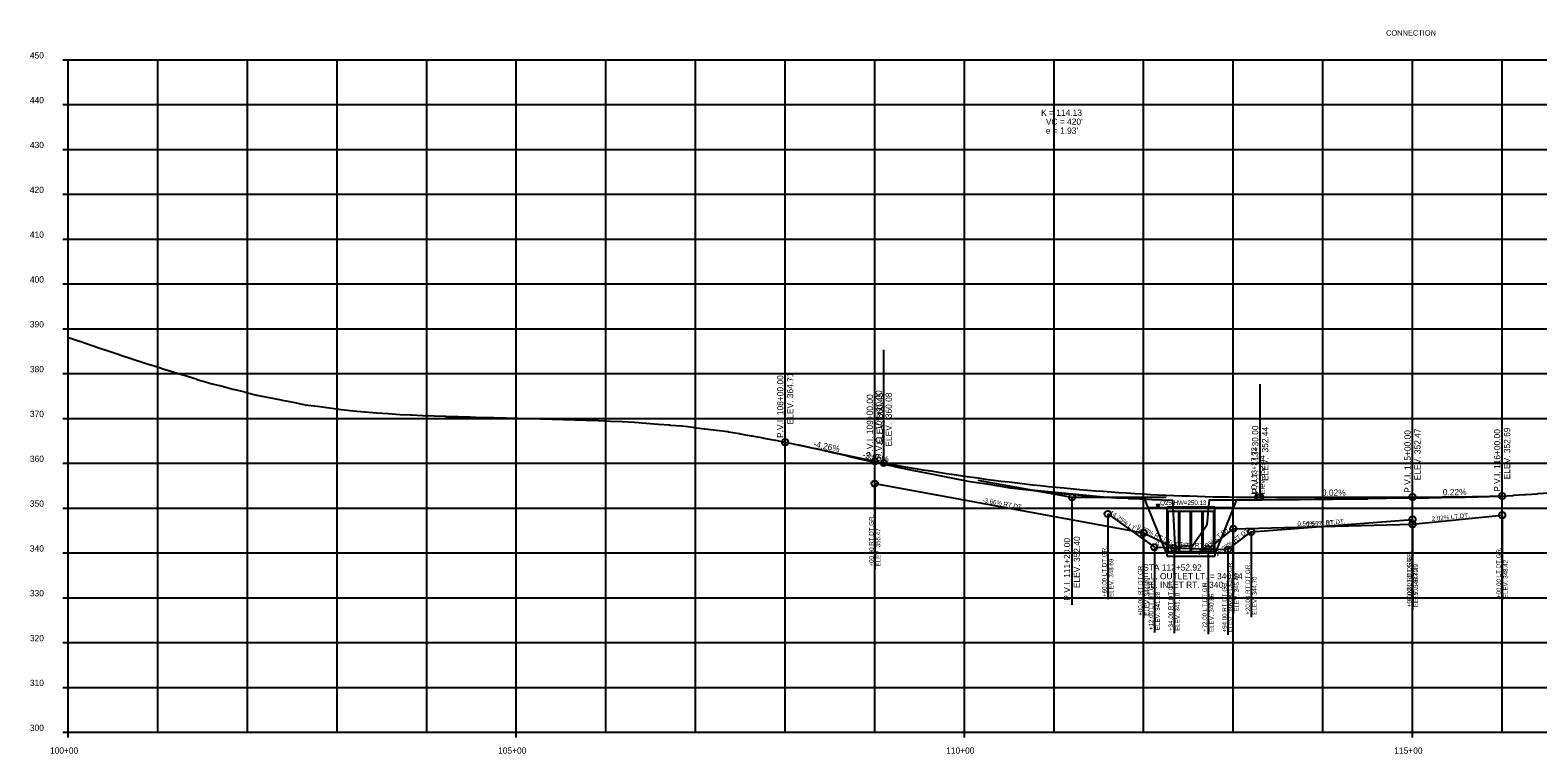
# Model space of a CAD drawing. Extents: x 1627557 to 1636561, y 783843 to 794002.
# Drawn here: x 1633050 to 1634732, y 793194 to 794002 of the extents above; entities that cross this region are included whole.
import ezdxf

# ---------------------------------------------------------------- set-up
doc = ezdxf.new("R2010")
doc.units = 0
for name, color, linetype in [('R_Axis', 7, 'Continuous'), ('R_Axis Annot', 7, 'Continuous'), ('R_Culvert', 7, 'Continuous'), ('R_Exist Surface', 7, 'Continuous'), ('R_Fin Surface', 7, 'Continuous'), ('R_Grid', 7, 'Continuous'), ('R_No Plot', 7, 'Continuous'), ('R_Vert Alg', 7, 'Continuous'), ('R_Vert Alg Annot', 7, 'Continuous'), ('R_Vert Alg LP', 7, 'Continuous'), ('R_Vert Alg LP Annot', 7, 'Continuous'), ('R_Vert Ditch Alg', 7, 'Continuous'), ('R_Vert Ditch Alg Annot', 7, 'Continuous'), ('RC Box Annot', 7, 'Continuous')]:
    doc.layers.add(name, color=color, linetype=linetype)

msp = doc.modelspace()

# ---------------------------------------------------------------- linework, layer by layer
at = {"layer": 'R_Axis'}
for p, q in [((1633086.6, 793968.6), (1633092.6, 793968.6)), ((1633086.6, 793968.6), (1633092.6, 793968.6)), ((1633092.6, 793218.6), (1633092.6, 793968.6)), ((1633086.6, 793918.6), (1633092.6, 793918.6)), ((1633086.6, 793868.6), (1633092.6, 793868.6)), ((1633086.6, 793818.6), (1633092.6, 793818.6)), ((1633086.6, 793768.6), (1633092.6, 793768.6)), ((1633086.6, 793718.6), (1633092.6, 793718.6)), ((1633086.6, 793668.6), (1633092.6, 793668.6)), ((1633086.6, 793618.6), (1633092.6, 793618.6)), ((1633086.6, 793568.6), (1633092.6, 793568.6)), ((1633086.6, 793518.6), (1633092.6, 793518.6)), ((1633086.6, 793468.6), (1633092.6, 793468.6)), ((1633086.6, 793418.6), (1633092.6, 793418.6)), ((1633086.6, 793368.6), (1633092.6, 793368.6)), ((1633086.6, 793318.6), (1633092.6, 793318.6)), ((1633086.6, 793268.6), (1633092.6, 793268.6)), ((1633086.6, 793218.6), (1633092.6, 793218.6)), ((1633092.6, 793218.6), (1636092.6, 793218.6)), ((1633092.6, 793212.6), (1633092.6, 793218.6)), ((1633592.6, 793212.6), (1633592.6, 793218.6)), ((1634092.6, 793212.6), (1634092.6, 793218.6)), ((1634592.6, 793212.6), (1634592.6, 793218.6))]:
    msp.add_line(p, q, dxfattribs=at)
at = {"layer": 'R_Culvert'}
for p, q in [((1634297.8, 793469.2), (1634393.2, 793469.2)), ((1634319, 793420), (1634319, 793470)), ((1634319, 793470), (1634372, 793470)), ((1634319, 793465), (1634372, 793465)), ((1634320, 793420), (1634320, 793465)), ((1634332, 793420), (1634332, 793465)), ((1634333, 793420), (1634333, 793465)), ((1634345, 793420), (1634345, 793465)), ((1634346, 793420), (1634346, 793465)), ((1634358, 793420), (1634358, 793465)), ((1634359, 793420), (1634359, 793465)), ((1634371, 793420), (1634371, 793465)), ((1634372, 793420), (1634372, 793470)), ((1634319, 793420), (1634372, 793420)), ((1634319, 793415), (1634319, 793420)), ((1634319, 793415), (1634372, 793415)), ((1634372, 793420), (1634372, 793415))]:
    msp.add_line(p, q, dxfattribs=at)
msp.add_lwpolyline([(1634308.5, 793469.2), (1634310.2, 793472.2), (1634306.8, 793472.2)], close=True, dxfattribs=at)
at = {"layer": 'R_Exist Surface'}
msp.add_lwpolyline([(1633092.6, 793659), (1633092.8, 793658.9), (1633105.4, 793654.6), (1633105.6, 793654.6), (1633118.3, 793650.3), (1633118.4, 793650.3), (1633131.1, 793646), (1633131.1, 793646), (1633132.8, 793645.4), (1633143.9, 793641.6), (1633144, 793641.6), (1633157.1, 793637.3), (1633157.2, 793637.3), (1633170.3, 793633), (1633170.5, 793633), (1633178.5, 793630.4), (1633183.5, 793628.8), (1633183.8, 793628.7), (1633196.6, 793624.5), (1633197, 793624.4), (1633209.9, 793620.4), (1633210.3, 793620.3), (1633223.2, 793616.4), (1633223.5, 793616.3), (1633236.4, 793612.3), (1633236.7, 793612.2), (1633249.7, 793608.2), (1633249.9, 793608.1), (1633263, 793604.8), (1633263.2, 793604.8), (1633276.3, 793601.4), (1633276.5, 793601.4), (1633289.6, 793598.1), (1633289.7, 793598), (1633302.8, 793594.7), (1633303, 793594.7), (1633316.5, 793592), (1633316.5, 793592), (1633330.1, 793589.3), (1633330.1, 793589.3), (1633331.2, 793589.1), (1633343.6, 793586.6), (1633343.6, 793586.6), (1633357.1, 793583.9), (1633357.2, 793583.9), (1633370.3, 793582.1), (1633370.5, 793582.1), (1633370.7, 793582.1), (1633383.8, 793580.4), (1633384, 793580.4), (1633397.1, 793578.6), (1633397.4, 793578.6), (1633410.4, 793576.9), (1633410.7, 793576.9), (1633423.4, 793575.9), (1633423.9, 793575.9), (1633436.5, 793575), (1633437, 793574.9), (1633449.5, 793574), (1633450.1, 793574), (1633462.6, 793573), (1633474.7, 793572.5), (1633475.3, 793572.5), (1633476, 793572.5), (1633488, 793572), (1633488.7, 793572), (1633500.8, 793571.5), (1633501.5, 793571.4), (1633513.5, 793571), (1633514.3, 793570.9), (1633527, 793570.6), (1633527.8, 793570.6), (1633540.6, 793570.2), (1633541.3, 793570.2), (1633554.1, 793569.8), (1633554.8, 793569.8), (1633567.6, 793569.5), (1633580, 793569.2), (1633580.6, 793569.2), (1633581.2, 793569.1), (1633593.6, 793568.8), (1633594.2, 793568.8), (1633606.7, 793568.5), (1633607.2, 793568.5), (1633619.7, 793568.2), (1633620.1, 793568.2), (1633632.5, 793567.8), (1633632.9, 793567.8), (1633645.4, 793567.4), (1633645.6, 793567.4), (1633658.2, 793567), (1633658.3, 793567), (1633670.6, 793566.7), (1633671, 793566.7), (1633671, 793566.7), (1633684.3, 793566.1), (1633684.4, 793566.1), (1633697.6, 793565.5), (1633697.8, 793565.5), (1633710.9, 793565), (1633711.2, 793565), (1633724.2, 793564.4), (1633724.6, 793564.4), (1633737.4, 793563.4), (1633737.9, 793563.3), (1633750.5, 793562.3), (1633751.1, 793562.3), (1633763.7, 793561.3), (1633764.4, 793561.2), (1633776.8, 793560.3), (1633777.6, 793560.2), (1633789.8, 793558.7), (1633790.6, 793558.6), (1633802.7, 793557.1), (1633803.5, 793557), (1633815.6, 793555.5), (1633816.4, 793555.4), (1633828.5, 793553.9), (1633829.3, 793553.8), (1633841.7, 793551.6), (1633842.4, 793551.4), (1633854.8, 793549.2), (1633855.6, 793549.1), (1633868, 793546.8), (1633868.7, 793546.7), (1633881.2, 793544.5), (1633881.8, 793544.4), (1633894.1, 793541.8), (1633894.6, 793541.7), (1633906.9, 793539.1), (1633907.5, 793539), (1633919.8, 793536.4), (1633920.3, 793536.3), (1633932.7, 793533.8), (1633933.2, 793533.7), (1633946.9, 793530.4), (1633947.3, 793530.3), (1633961, 793527.1), (1633961.5, 793527), (1633961.6, 793527), (1633975.3, 793523.7), (1633975.7, 793523.6), (1633989.5, 793520.4), (1633989.8, 793520.3), (1634013.7, 793515.2), (1634014.1, 793515.1), (1634038.1, 793510), (1634038.4, 793510), (1634051.5, 793507.4), (1634051.6, 793507.4), (1634051.7, 793507.4), (1634064.8, 793504.8), (1634064.8, 793504.8), (1634077.9, 793502.2), (1634078, 793502.2), (1634085.3, 793500.8), (1634091.1, 793499.6), (1634091.1, 793499.6), (1634096.3, 793498.8), (1634104.3, 793497.5), (1634104.4, 793497.5), (1634117.5, 793495.5), (1634130.6, 793493.4), (1634130.8, 793493.4), (1634143.8, 793491.3), (1634144, 793491.3), (1634157.2, 793489.8), (1634157.4, 793489.8), (1634170.5, 793488.2), (1634170.8, 793488.2), (1634183.9, 793486.7), (1634184.2, 793486.6), (1634184.5, 793486.6), (1634197.6, 793485.1), (1634198, 793485), (1634210.5, 793484), (1634223.2, 793482.9), (1634223.5, 793482.9), (1634236.2, 793481.8), (1634236.4, 793481.8), (1634249.2, 793480.7), (1634249.4, 793480.7), (1634262.5, 793480.1), (1634262.6, 793480.1), (1634275.8, 793479.5), (1634275.8, 793479.4), (1634275.9, 793479.4), (1634281.9, 793479.2), (1634289, 793478.8), (1634289.1, 793478.8), (1634302.2, 793478.2), (1634302.3, 793478.2), (1634324.5, 793477.6), (1634324.8, 793477.6), (1634327.5, 793426), (1634327.6, 793424.5), (1634327.6, 793424.5), (1634327.9, 793424.5), (1634338.5, 793427), (1634346.7, 793426.3), (1634362.8, 793449), (1634363.2, 793449.2), (1634363.3, 793450), (1634363.4, 793450.2), (1634366, 793477.7), (1634379.2, 793477.7), (1634379.4, 793477.7), (1634392.6, 793477.7), (1634392.8, 793477.7), (1634393, 793477.7), (1634406.2, 793477.8), (1634406.3, 793477.8), (1634419.6, 793477.8), (1634419.7, 793477.8), (1634441.3, 793478), (1634441.4, 793478), (1634463.1, 793478.3), (1634463.1, 793478.3), (1634463.1, 793478.3), (1634466.4, 793478.3), (1634483, 793478.5), (1634483.1, 793478.5), (1634502.8, 793478.7), (1634503, 793478.7), (1634503.2, 793478.7), (1634522.8, 793478.9), (1634523.1, 793478.9), (1634542.5, 793479), (1634542.9, 793479), (1634543.3, 793479.1), (1634563.2, 793479.5), (1634563.6, 793479.5), (1634583.4, 793479.9), (1634583.8, 793479.9), (1634596.7, 793480.1), (1634597.4, 793480.1), (1634610.2, 793480.2), (1634611, 793480.2), (1634623.8, 793480.4), (1634624.7, 793480.4), (1634637.4, 793480.6), (1634638.4, 793480.6), (1634651.2, 793480.9), (1634663.9, 793481.3), (1634665.2, 793481.3), (1634677.9, 793481.6), (1634679.3, 793481.7), (1634692, 793482), (1634704.5, 793482.8), (1634705.4, 793482.9), (1634718.1, 793483.7), (1634718.9, 793483.8), (1634731.6, 793484.6), (1634732.4, 793484.7), (1634745.1, 793485.5)], dxfattribs=at)
at = {"layer": 'R_Fin Surface'}
for p, q in [((1634373.5, 793420), (1634396.6, 793477.7)), ((1634372, 793420), (1634373.5, 793420))]:
    msp.add_line(p, q, dxfattribs=at)
msp.add_lwpolyline([(1634319, 793420), (1634317.5, 793420), (1634294, 793478.6)], dxfattribs=at)
at = {"layer": 'R_Grid'}
for p, q in [((1633092.6, 793968.6), (1636092.6, 793968.6)), ((1633092.6, 793968.6), (1636092.6, 793968.6)), ((1633192.6, 793218.6), (1633192.6, 793968.6)), ((1633292.6, 793218.6), (1633292.6, 793968.6)), ((1633392.6, 793218.6), (1633392.6, 793968.6)), ((1633492.6, 793218.6), (1633492.6, 793968.6)), ((1633592.6, 793218.6), (1633592.6, 793968.6)), ((1633692.6, 793218.6), (1633692.6, 793968.6)), ((1633792.6, 793218.6), (1633792.6, 793968.6)), ((1633892.6, 793218.6), (1633892.6, 793968.6)), ((1633992.6, 793218.6), (1633992.6, 793968.6)), ((1634092.6, 793218.6), (1634092.6, 793968.6)), ((1634192.6, 793218.6), (1634192.6, 793968.6)), ((1634292.6, 793218.6), (1634292.6, 793968.6)), ((1634392.6, 793218.6), (1634392.6, 793968.6)), ((1634492.6, 793218.6), (1634492.6, 793968.6)), ((1634592.6, 793218.6), (1634592.6, 793968.6)), ((1634692.6, 793218.6), (1634692.6, 793968.6)), ((1633092.6, 793918.6), (1636092.6, 793918.6)), ((1633092.6, 793868.6), (1636092.6, 793868.6)), ((1633092.6, 793818.6), (1636092.6, 793818.6)), ((1633092.6, 793768.6), (1636092.6, 793768.6)), ((1633092.6, 793718.6), (1636092.6, 793718.6)), ((1633092.6, 793668.6), (1636092.6, 793668.6)), ((1633092.6, 793618.6), (1636092.6, 793618.6)), ((1633092.6, 793568.6), (1636092.6, 793568.6)), ((1633092.6, 793518.6), (1636092.6, 793518.6)), ((1633092.6, 793468.6), (1636092.6, 793468.6)), ((1633092.6, 793418.6), (1636092.6, 793418.6)), ((1633092.6, 793368.6), (1636092.6, 793368.6)), ((1633092.6, 793318.6), (1636092.6, 793318.6)), ((1633092.6, 793268.6), (1636092.6, 793268.6))]:
    msp.add_line(p, q, dxfattribs=at)
at = {"layer": 'R_Vert Alg'}
for p, q in [((1633892.6, 793542.1), (1633892.6, 793662.1)), ((1634002.6, 793519), (1634002.6, 793645)), ((1633992.6, 793520.8), (1633992.6, 793640.8)), ((1634422.6, 793480.8), (1634422.6, 793606.8)), ((1634592.6, 793480.9), (1634592.6, 793600.9)), ((1634692.6, 793482), (1634692.6, 793602)), ((1633892.6, 793542.1), (1633992.6, 793520.8)), ((1633992.6, 793520.8), (1634002.6, 793519)), ((1634107.6, 793499.8), (1634212.6, 793480.6)), ((1634212.6, 793480.6), (1634317.6, 793480.7)), ((1634212.6, 793480.6), (1634212.6, 793360.6)), ((1634422.6, 793480.8), (1634592.6, 793480.9)), ((1634592.6, 793480.9), (1634692.6, 793482))]:
    msp.add_line(p, q, dxfattribs=at)
msp.add_lwpolyline([(1634002.6, 793519), (1634011.3, 793517.4), (1634020.1, 793515.9), (1634028.8, 793514.3), (1634037.6, 793512.9), (1634046.3, 793511.4), (1634055.1, 793510), (1634063.8, 793508.6), (1634072.6, 793507.3), (1634081.3, 793505.9), (1634090.1, 793504.7), (1634098.8, 793503.4), (1634107.6, 793502.2), (1634116.3, 793501), (1634125.1, 793499.9), (1634133.8, 793498.8), (1634142.6, 793497.7), (1634151.3, 793496.6), (1634160.1, 793495.6), (1634168.8, 793494.6), (1634177.6, 793493.7), (1634186.3, 793492.8), (1634195.1, 793491.9), (1634203.8, 793491), (1634221.3, 793489.4), (1634230.1, 793488.7), (1634238.8, 793488), (1634247.6, 793487.3), (1634256.3, 793486.7), (1634265.1, 793486.1), (1634273.8, 793485.5), (1634282.6, 793484.9), (1634291.3, 793484.4), (1634300.1, 793483.9), (1634308.8, 793483.5), (1634317.6, 793483.1), (1634326.3, 793482.7), (1634335.1, 793482.4), (1634343.8, 793482.1), (1634352.6, 793481.8), (1634361.3, 793481.5), (1634370.1, 793481.3), (1634378.8, 793481.2), (1634387.6, 793481), (1634396.3, 793480.9), (1634405.1, 793480.8), (1634413.8, 793480.8), (1634422.6, 793480.8)], dxfattribs=at)
for centre in [(1633892.6, 793542.1), (1633992.6, 793520.8), (1634002.6, 793519), (1634212.6, 793480.6), (1634422.6, 793480.8), (1634592.6, 793480.9), (1634692.6, 793482)]:
    msp.add_circle(centre, 3.5, dxfattribs=at)
at = {"layer": 'R_Vert Alg Annot'}
msp.add_line((1634151.6, 793490.4), (1634251.6, 793480.6), dxfattribs=at)
at = {"layer": 'R_Vert Alg LP'}
msp.add_circle((1634420.3, 793480.8), 3.5, dxfattribs=at)
at = {"layer": 'R_Vert Ditch Alg'}
for p, q in [((1633992.6, 793495.9), (1633992.6, 793485.9)), ((1633992.6, 793495.9), (1634292.6, 793441)), ((1633992.6, 793485.9), (1633992.6, 793400.9)), ((1634252.6, 793462), (1634252.6, 793452)), ((1634252.6, 793462), (1634304.6, 793425)), ((1634592.6, 793450.6), (1634692.6, 793460.7)), ((1634692.6, 793460.7), (1634692.6, 793450.7)), ((1634252.6, 793452), (1634252.6, 793367)), ((1634364.6, 793422.9), (1634392.6, 793445.6)), ((1634392.6, 793445.6), (1634592.6, 793450.6)), ((1634392.6, 793445.6), (1634392.6, 793435.6)), ((1634412.6, 793442.1), (1634592.6, 793456)), ((1634592.6, 793456), (1634592.6, 793446)), ((1634592.6, 793450.6), (1634592.6, 793440.6)), ((1634592.6, 793446), (1634592.6, 793361)), ((1634692.6, 793450.7), (1634692.6, 793365.7)), ((1634292.6, 793441), (1634292.6, 793431)), ((1634292.6, 793441), (1634326.6, 793424.1)), ((1634292.6, 793431), (1634292.6, 793346)), ((1634386.6, 793422.3), (1634412.6, 793442.1)), ((1634392.6, 793435.6), (1634392.6, 793350.6)), ((1634412.6, 793442.1), (1634412.6, 793432.1)), ((1634412.6, 793432.1), (1634412.6, 793347.1)), ((1634592.6, 793440.6), (1634592.6, 793355.6)), ((1634304.6, 793425), (1634304.6, 793415)), ((1634304.6, 793425), (1634364.6, 793422.9)), ((1634304.6, 793415), (1634304.6, 793330)), ((1634326.6, 793424.1), (1634326.6, 793414.1)), ((1634326.6, 793424.1), (1634386.6, 793422.3)), ((1634326.6, 793414.1), (1634326.6, 793329.1)), ((1634364.6, 793422.9), (1634364.6, 793412.9)), ((1634364.6, 793412.9), (1634364.6, 793327.9)), ((1634386.6, 793422.3), (1634386.6, 793412.3)), ((1634386.6, 793412.3), (1634386.6, 793327.3))]:
    msp.add_line(p, q, dxfattribs=at)
for centre in [(1633992.6, 793495.9), (1634252.6, 793462), (1634592.6, 793456), (1634692.6, 793460.7), (1634292.6, 793441), (1634392.6, 793445.6), (1634412.6, 793442.1), (1634592.6, 793450.6), (1634304.6, 793425), (1634326.6, 793424.1), (1634364.6, 793422.9), (1634386.6, 793422.3)]:
    msp.add_circle(centre, 3.5, dxfattribs=at)

# ---------------------------------------------------------------- texts
at = {"layer": 'R_Axis Annot'}
for s, p in [('450', (1633049.9, 793970.1)), ('450', (1633049.9, 793970.1)), ('440', (1633049.9, 793920.1)), ('430', (1633049.9, 793870.1)), ('420', (1633049.9, 793820.1)), ('410', (1633049.9, 793770.1)), ('400', (1633049.9, 793720.1)), ('390', (1633049.9, 793670.1)), ('380', (1633049.9, 793620.1)), ('370', (1633049.9, 793570.1)), ('360', (1633049.9, 793520.1)), ('350', (1633049.9, 793470.1)), ('340', (1633049.9, 793420.1)), ('330', (1633049.9, 793370.1)), ('320', (1633049.9, 793320.1)), ('310', (1633049.9, 793270.1)), ('300', (1633049.9, 793220.1)), ('100+00', (1633072.3, 793194.6)), ('105+00', (1633572.3, 793194.6)), ('110+00', (1634072.3, 793194.6)), ('115+00', (1634572.3, 793194.6))]:
    msp.add_text(s, height=7, dxfattribs=at).set_placement(p)
at = {"layer": 'R_Culvert'}
msp.add_text('Q25 HW=250.13', height=5, dxfattribs=at).set_placement((1634311, 793472.1))
at = {"layer": 'R_No Plot'}
msp.add_text('CONNECTION', height=6, dxfattribs=at).set_placement((1634563.1, 793995.6))
at = {"layer": 'R_Vert Alg Annot'}
for s, p in [('K = 114.13', (1634178.2, 793906.1)), ("VC = 420'", (1634183.5, 793896.1)), ("e = 1.93'", (1634183.5, 793886.1))]:
    msp.add_text(s, height=7, dxfattribs=at).set_placement(p)
for s, rotation, p in [('P.V.I. 108+00.00', 90, (1633890.6, 793546.8)), ('ELEV. 364.71', 90, (1633901.6, 793562)), ('P.V.I. 109+00.00', 90, (1633990.6, 793525.5)), ('P.V.C . 109+10.00', 90, (1634000.6, 793523.2)), ('ELEV. 360.45', 90, (1634001.6, 793539.5)), ('ELEV.  360.08', 90, (1634011.6, 793537.1)), ('P.V.T.  113+30.00', 90, (1634420.6, 793485)), ('ELEV.  352.44', 90, (1634431.6, 793498.9)), ('P.V.I. 115+00.00', 90, (1634590.6, 793485.6)), ('ELEV. 352.47', 90, (1634601.6, 793499.6)), ('P.V.I. 116+00.00', 90, (1634690.6, 793486.7)), ('ELEV. 352.69', 90, (1634701.6, 793500.7)), ('-4.26%', 347.9757, (1633923.7, 793537)), ('-3.66%', 349.6296, (1633978.5, 793524.9)), ('0.02%', 0.0573, (1634491.5, 793482.3)), ('0.22%', 0.6302, (1634626.4, 793482.8)), ('P.V.I. 111+20.00', 90, (1634210.6, 793365.3)), ('ELEV. 352.40', 90, (1634221.6, 793379.3))]:
    msp.add_text(s, height=7, rotation=rotation, dxfattribs=at).set_placement(p)
at = {"layer": 'R_Vert Alg LP Annot'}
for s, p in [('LO 113+27.72', (1634418.8, 793483.8)), ('Elev 352.44', (1634427.8, 793483.8))]:
    msp.add_text(s, height=6, rotation=90, dxfattribs=at).set_placement(p)
at = {"layer": 'R_Vert Ditch Alg Annot'}
for s, rotation, p in [('-3.66% RT.DT.', 349.6296, (1634112.5, 793475.2)), ('-14.25% LT.DT.', 324.5301, (1634252.2, 793463.8)), ('2.02% LT.DT.', 5.7673, (1634614.3, 793454)), ('+00.00 RT.DT.GR.', 90, (1633991.3, 793403.4)), ('ELEV. 355.47', 90, (1633998.8, 793403.4)), ('-9.97% RT.DT.', 333.5024, (1634282.6, 793447.4)), ('16.21% LT.DT.', 39.0322, (1634353.9, 793415.8)), ('15.23% RT.DT.', 37.2907, (1634374.3, 793414.5)), ('0.50% LT.DT.', 1.4321, (1634464.3, 793448.6)), ('1.55% RT.DT.', 4.4316, (1634474.3, 793448.1)), ('-0.70% LT.DT.', 357.9955, (1634303.9, 793426.3)), ('-0.60% RT.DT.', 358.2816, (1634325.9, 793425.4)), ('+60.00 LT.DT.GR.', 90, (1634251.3, 793369.5)), ('ELEV. 348.69', 90, (1634258.8, 793369.5)), ('+00.00 RT.DT.GR.', 90, (1634591.3, 793363.5)), ('+00.00 LT.DT.GR.', 90, (1634591.3, 793358.1)), ('+00.00 LT.DT.GR.', 90, (1634691.3, 793368.2)), ('ELEV. 348.42', 90, (1634698.8, 793368.2)), ('+00.00 RT.DT.GR.', 90, (1634291.3, 793348.5)), ('+00.00 LT.DT.GR.', 90, (1634391.3, 793353.1)), ('ELEV. 345.40', 90, (1634398.8, 793353.1)), ('+20.00 RT.DT.GR.', 90, (1634411.3, 793349.6)), ('ELEV. 347.49', 90, (1634598.8, 793363.5)), ('ELEV. 346.40', 90, (1634598.8, 793358.1)), ('ELEV. 344.49', 90, (1634298.8, 793348.5)), ('+12.00 LT.DT.GR.', 90, (1634303.3, 793332.5)), ('+34.00 RT.DT.GR.', 90, (1634325.3, 793331.6)), ('+72.00 LT.DT.GR.', 90, (1634363.3, 793330.4)), ('+94.00 RT.DT.GR.', 90, (1634385.3, 793329.8)), ('ELEV. 344.70', 90, (1634418.8, 793349.6)), ('ELEV. 341.28', 90, (1634310.8, 793332.5)), ('ELEV. 341.10', 90, (1634332.8, 793331.6)), ('ELEV. 340.86', 90, (1634370.8, 793330.4)), ('ELEV. 340.74', 90, (1634392.8, 793329.8))]:
    msp.add_text(s, height=5, rotation=rotation, dxfattribs=at).set_placement(p)
at = {"layer": 'RC Box Annot'}
for s, p in [('STA 112+52.92', (1634292.1, 793398.9)), ('F.L. OUTLET LT. = 340.14', (1634292.1, 793389.2)), ('F.L. INLET RT. = 340.40', (1634292.1, 793379.6))]:
    msp.add_text(s, height=7, dxfattribs=at).set_placement(p)

doc.saveas('drawing.dxf')
